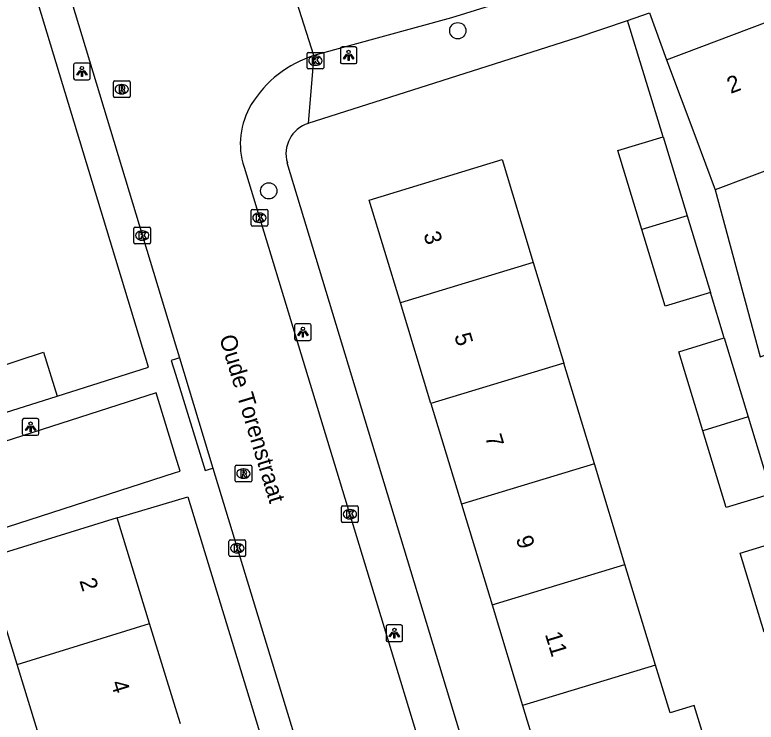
# Model space of a CAD drawing. Extents: x 161253 to 161848, y 384872 to 385383.
# Drawn here: x 161490.34 to 161534.89, y 385004.39 to 385046.88 of the extents above; entities that cross this region are included whole.
import ezdxf

# ---------------------------------------------------------------- set-up
doc = ezdxf.new("R2010")
doc.units = 0
for name, color, linetype in [('IMGEO_Boom', 7, 'Continuous'), ('IMGEO_Kolk', 7, 'Continuous'), ('IMGEO_Lichtpunt', 7, 'Continuous'), ('IMGEO_Openbare_ruimte_label', 7, 'Continuous'), ('IMGEO_Pand', 7, 'Continuous'), ('IMGEO_Pand_nummerreeks', 7, 'Continuous'), ('IMGEO_Rijbaan_lokaal_open', 7, 'Continuous'), ('IMGEO_Rioolput', 7, 'Continuous'), ('IMGEO_Voetpad_open', 7, 'Continuous')]:
    doc.layers.add(name, color=color, linetype=linetype)

msp = doc.modelspace()

# ---------------------------------------------------------------- linework, layer by layer
at = {"layer": 'IMGEO_Boom'}
for centre in [(161516.961, 385045.927), (161505.603, 385036.307)]:
    msp.add_circle(centre, 0.489, dxfattribs=at)
at = {"layer": 'IMGEO_Kolk'}
for p, q in [((161507.901, 385043.701), (161507.901, 385044.553)), ((161507.976, 385044.627), (161508.828, 385044.627)), ((161508.389, 385044.407), (161508.414, 385044.407)), ((161508.902, 385044.553), (161508.902, 385043.701)), ((161508.412, 385043.847), (161508.387, 385043.847)), ((161508.828, 385043.627), (161507.976, 385043.627)), ((161504.541, 385034.269), (161504.541, 385035.121)), ((161504.616, 385035.195), (161505.468, 385035.195)), ((161505.029, 385034.975), (161505.054, 385034.975)), ((161505.542, 385035.121), (161505.542, 385034.269)), ((161505.052, 385034.415), (161505.027, 385034.415)), ((161497.497, 385033.196), (161497.497, 385034.048)), ((161497.572, 385034.122), (161498.424, 385034.122)), ((161498.498, 385034.048), (161498.498, 385033.196)), ((161505.468, 385034.195), (161504.616, 385034.195)), ((161497.985, 385033.902), (161498.01, 385033.902)), ((161498.424, 385033.122), (161497.572, 385033.122)), ((161498.008, 385033.342), (161497.983, 385033.342)), ((161509.976, 385016.457), (161509.976, 385017.309)), ((161510.051, 385017.383), (161510.903, 385017.383)), ((161510.464, 385017.163), (161510.489, 385017.163)), ((161510.977, 385017.309), (161510.977, 385016.457)), ((161510.487, 385016.603), (161510.462, 385016.603)), ((161510.903, 385016.383), (161510.051, 385016.383)), ((161503.212, 385014.414), (161503.212, 385015.266)), ((161503.287, 385015.34), (161504.139, 385015.34)), ((161504.213, 385015.266), (161504.213, 385014.414)), ((161503.7, 385015.12), (161503.725, 385015.12)), ((161503.723, 385014.56), (161503.698, 385014.56)), ((161504.139, 385014.34), (161503.287, 385014.34))]:
    msp.add_line(p, q, dxfattribs=at)
for points in [[(161507.901, 385043.701), (161507.901, 385044.553)], [(161507.976, 385044.627), (161508.828, 385044.627)], [(161508.222, 385044.327), (161508.345, 385044.327), (161508.345, 385044.176), (161508.475, 385044.327), (161508.639, 385044.327), (161508.493, 385044.176), (161508.646, 385043.927), (161508.494, 385043.927), (161508.409, 385044.091), (161508.345, 385044.024), (161508.345, 385043.927), (161508.222, 385043.927), (161508.222, 385044.327)], [(161508.902, 385044.553), (161508.902, 385043.701)], [(161508.828, 385043.627), (161507.976, 385043.627)], [(161504.541, 385034.269), (161504.541, 385035.121)], [(161504.616, 385035.195), (161505.468, 385035.195)], [(161504.862, 385034.895), (161504.985, 385034.895), (161504.985, 385034.744), (161505.115, 385034.895), (161505.279, 385034.895), (161505.133, 385034.744), (161505.286, 385034.495), (161505.134, 385034.495), (161505.049, 385034.659), (161504.985, 385034.592), (161504.985, 385034.495), (161504.862, 385034.495), (161504.862, 385034.895)], [(161505.542, 385035.121), (161505.542, 385034.269)], [(161497.497, 385033.196), (161497.497, 385034.048)], [(161497.572, 385034.122), (161498.424, 385034.122)], [(161498.498, 385034.048), (161498.498, 385033.196)], [(161505.468, 385034.195), (161504.616, 385034.195)], [(161497.818, 385033.822), (161497.941, 385033.822), (161497.941, 385033.671), (161498.071, 385033.822), (161498.235, 385033.822), (161498.089, 385033.671), (161498.242, 385033.422), (161498.09, 385033.422), (161498.005, 385033.586), (161497.941, 385033.519), (161497.941, 385033.422), (161497.818, 385033.422), (161497.818, 385033.822)], [(161498.424, 385033.122), (161497.572, 385033.122)], [(161509.976, 385016.457), (161509.976, 385017.309)], [(161510.051, 385017.383), (161510.903, 385017.383)], [(161510.297, 385017.083), (161510.42, 385017.083), (161510.42, 385016.932), (161510.55, 385017.083), (161510.714, 385017.083), (161510.568, 385016.932), (161510.721, 385016.683), (161510.569, 385016.683), (161510.484, 385016.847), (161510.42, 385016.78), (161510.42, 385016.683), (161510.297, 385016.683), (161510.297, 385017.083)], [(161510.977, 385017.309), (161510.977, 385016.457)], [(161510.903, 385016.383), (161510.051, 385016.383)], [(161503.212, 385014.414), (161503.212, 385015.266)], [(161503.287, 385015.34), (161504.139, 385015.34)], [(161504.213, 385015.266), (161504.213, 385014.414)], [(161503.533, 385015.04), (161503.656, 385015.04), (161503.656, 385014.889), (161503.786, 385015.04), (161503.95, 385015.04), (161503.804, 385014.889), (161503.957, 385014.64), (161503.805, 385014.64), (161503.72, 385014.804), (161503.656, 385014.737), (161503.656, 385014.64), (161503.533, 385014.64), (161503.533, 385015.04)], [(161504.139, 385014.34), (161503.287, 385014.34)]]:
    msp.add_lwpolyline(points, dxfattribs=at)
for centre, start, end in [((161507.978, 385044.551), 91.552, 178.448), ((161507.978, 385044.551), 91.552, 178.448), ((161508.826, 385044.551), 1.552, 88.448), ((161508.826, 385044.551), 1.552, 88.448), ((161507.978, 385043.703), 181.552, 268.448), ((161507.978, 385043.703), 181.552, 268.448), ((161508.826, 385043.703), 271.552, 358.448), ((161508.826, 385043.703), 271.552, 358.448), ((161504.618, 385035.119), 91.552, 178.448), ((161504.618, 385035.119), 91.552, 178.448), ((161505.466, 385035.119), 1.552, 88.448), ((161505.466, 385035.119), 1.552, 88.448), ((161497.574, 385034.046), 91.552, 178.448), ((161497.574, 385034.046), 91.552, 178.448), ((161498.422, 385034.046), 1.552, 88.448), ((161498.422, 385034.046), 1.552, 88.448), ((161504.618, 385034.271), 181.552, 268.448), ((161504.618, 385034.271), 181.552, 268.448), ((161505.466, 385034.271), 271.552, 358.448), ((161505.466, 385034.271), 271.552, 358.448), ((161497.574, 385033.198), 181.552, 268.448), ((161497.574, 385033.198), 181.552, 268.448), ((161498.422, 385033.198), 271.552, 358.448), ((161498.422, 385033.198), 271.552, 358.448), ((161510.053, 385017.307), 91.552, 178.448), ((161510.053, 385017.307), 91.552, 178.448), ((161510.901, 385017.307), 1.552, 88.448), ((161510.901, 385017.307), 1.552, 88.448), ((161510.053, 385016.459), 181.552, 268.448), ((161510.053, 385016.459), 181.552, 268.448), ((161510.901, 385016.459), 271.552, 358.448), ((161510.901, 385016.459), 271.552, 358.448), ((161503.289, 385015.264), 91.552, 178.448), ((161503.289, 385015.264), 91.552, 178.448), ((161504.137, 385015.264), 1.552, 88.448), ((161504.137, 385015.264), 1.552, 88.448), ((161503.289, 385014.416), 181.552, 268.448), ((161503.289, 385014.416), 181.552, 268.448), ((161504.137, 385014.416), 271.552, 358.448), ((161504.137, 385014.416), 271.552, 358.448)]:
    msp.add_arc(centre, 0.0765, start, end, dxfattribs=at)
for centre, major_axis, ratio, start_param, end_param in [((161508.388, 385044.127), (-0.387, 0.002), 0.722429, 4.712389, 7.853982), ((161508.413, 385044.127), (-0.39, 0.002), 0.717154, 1.570796, 4.712389), ((161505.028, 385034.695), (-0.387, 0.002), 0.722429, 4.712389, 7.853982), ((161505.053, 385034.695), (-0.39, 0.002), 0.717154, 1.570796, 4.712389), ((161497.984, 385033.622), (-0.387, 0.002), 0.722429, 4.712389, 7.853982), ((161498.009, 385033.622), (-0.39, 0.002), 0.717154, 1.570796, 4.712389), ((161510.463, 385016.883), (-0.387, 0.002), 0.722429, 4.712389, 7.853982), ((161510.488, 385016.883), (-0.39, 0.002), 0.717154, 1.570796, 4.712389), ((161503.699, 385014.84), (-0.387, 0.002), 0.722429, 4.712389, 7.853982), ((161503.724, 385014.84), (-0.39, 0.002), 0.717154, 1.570796, 4.712389)]:
    msp.add_ellipse(centre, major_axis=major_axis, ratio=ratio, start_param=start_param, end_param=end_param, dxfattribs=at)
at = {"layer": 'IMGEO_Lichtpunt'}
for p, q in [((161509.902, 385044.853), (161509.902, 385044.046)), ((161509.902, 385044.853), (161509.902, 385044.046)), ((161510.804, 385044.948), (161509.996, 385044.948)), ((161510.804, 385044.948), (161509.996, 385044.948)), ((161510.898, 385044.046), (161510.898, 385044.853)), ((161510.898, 385044.046), (161510.898, 385044.853)), ((161493.878, 385043.881), (161493.878, 385043.074)), ((161493.878, 385043.881), (161493.878, 385043.074)), ((161494.78, 385043.976), (161493.972, 385043.976)), ((161494.78, 385043.976), (161493.972, 385043.976)), ((161494.874, 385043.074), (161494.874, 385043.881)), ((161494.874, 385043.074), (161494.874, 385043.881)), ((161509.996, 385043.952), (161510.804, 385043.952)), ((161509.996, 385043.952), (161510.804, 385043.952)), ((161493.972, 385042.98), (161494.78, 385042.98)), ((161493.972, 385042.98), (161494.78, 385042.98)), ((161507.155, 385028.228), (161507.155, 385027.421)), ((161507.155, 385028.228), (161507.155, 385027.421)), ((161508.057, 385028.323), (161507.249, 385028.323)), ((161508.057, 385028.323), (161507.249, 385028.323)), ((161508.151, 385027.421), (161508.151, 385028.228)), ((161508.151, 385027.421), (161508.151, 385028.228)), ((161507.249, 385027.327), (161508.057, 385027.327)), ((161507.249, 385027.327), (161508.057, 385027.327)), ((161490.794, 385022.534), (161490.794, 385021.727)), ((161490.794, 385022.534), (161490.794, 385021.727)), ((161491.696, 385022.629), (161490.888, 385022.629)), ((161491.696, 385022.629), (161490.888, 385022.629)), ((161491.79, 385021.727), (161491.79, 385022.534)), ((161491.79, 385021.727), (161491.79, 385022.534)), ((161490.888, 385021.633), (161491.696, 385021.633)), ((161490.888, 385021.633), (161491.696, 385021.633)), ((161512.649, 385010.134), (161512.649, 385009.327)), ((161512.649, 385010.134), (161512.649, 385009.327)), ((161513.551, 385010.229), (161512.743, 385010.229)), ((161513.551, 385010.229), (161512.743, 385010.229)), ((161513.645, 385009.327), (161513.645, 385010.134)), ((161513.645, 385009.327), (161513.645, 385010.134)), ((161512.743, 385009.233), (161513.551, 385009.233)), ((161512.743, 385009.233), (161513.551, 385009.233))]:
    msp.add_line(p, q, dxfattribs=at)
for points in [[(161510.276, 385044.517), (161510.315, 385044.489), (161510.127, 385044.227), (161510.089, 385044.254), (161510.276, 385044.517)], [(161510.378, 385044.469), (161510.425, 385044.469), (161510.425, 385044.147), (161510.378, 385044.147), (161510.378, 385044.469)], [(161510.488, 385044.489), (161510.526, 385044.516), (161510.713, 385044.254), (161510.674, 385044.226), (161510.488, 385044.489)], [(161494.252, 385043.545), (161494.291, 385043.517), (161494.103, 385043.255), (161494.065, 385043.282), (161494.252, 385043.545)], [(161494.354, 385043.497), (161494.401, 385043.497), (161494.401, 385043.175), (161494.354, 385043.175), (161494.354, 385043.497)], [(161494.464, 385043.517), (161494.502, 385043.544), (161494.689, 385043.282), (161494.65, 385043.254), (161494.464, 385043.517)], [(161507.529, 385027.892), (161507.568, 385027.864), (161507.38, 385027.602), (161507.342, 385027.629), (161507.529, 385027.892)], [(161507.631, 385027.844), (161507.678, 385027.844), (161507.678, 385027.522), (161507.631, 385027.522), (161507.631, 385027.844)], [(161507.741, 385027.864), (161507.779, 385027.891), (161507.966, 385027.629), (161507.927, 385027.601), (161507.741, 385027.864)], [(161491.168, 385022.198), (161491.207, 385022.17), (161491.019, 385021.908), (161490.981, 385021.935), (161491.168, 385022.198)], [(161491.27, 385022.15), (161491.317, 385022.15), (161491.317, 385021.828), (161491.27, 385021.828), (161491.27, 385022.15)], [(161491.38, 385022.17), (161491.418, 385022.197), (161491.605, 385021.935), (161491.566, 385021.907), (161491.38, 385022.17)], [(161513.023, 385009.798), (161513.062, 385009.77), (161512.874, 385009.508), (161512.836, 385009.535), (161513.023, 385009.798)], [(161513.125, 385009.75), (161513.172, 385009.75), (161513.172, 385009.428), (161513.125, 385009.428), (161513.125, 385009.75)], [(161513.235, 385009.77), (161513.273, 385009.797), (161513.46, 385009.535), (161513.421, 385009.507), (161513.235, 385009.77)]]:
    msp.add_lwpolyline(points, dxfattribs=at)
for centre in [(161510.401, 385044.651), (161494.377, 385043.679), (161507.654, 385028.026), (161491.293, 385022.332), (161513.148, 385009.932)]:
    msp.add_circle(centre, 0.0994, dxfattribs=at)
for centre, start, end in [((161509.996, 385044.853), 90, 180), ((161509.996, 385044.853), 90, 180), ((161510.804, 385044.853), 0, 90), ((161510.804, 385044.853), 0, 90), ((161493.972, 385043.881), 90, 180), ((161493.972, 385043.881), 90, 180), ((161494.78, 385043.881), 0, 90), ((161494.78, 385043.881), 0, 90), ((161509.996, 385044.046), 180, 270), ((161509.996, 385044.046), 180, 270), ((161510.804, 385044.046), 270, 0), ((161510.804, 385044.046), 270, 360), ((161493.972, 385043.074), 180, 270), ((161493.972, 385043.074), 180, 270), ((161494.78, 385043.074), 270, 0), ((161494.78, 385043.074), 270, 360), ((161507.249, 385028.228), 90, 180), ((161507.249, 385028.228), 90, 180), ((161508.057, 385028.228), 0, 90), ((161508.057, 385028.228), 0, 90), ((161507.249, 385027.421), 180, 270), ((161507.249, 385027.421), 180, 270), ((161508.057, 385027.421), 270, 0), ((161508.057, 385027.421), 270, 360), ((161490.888, 385022.534), 90, 180), ((161490.888, 385022.534), 90, 180), ((161491.696, 385022.534), 0, 90), ((161491.696, 385022.534), 0, 90), ((161490.888, 385021.727), 180, 270), ((161490.888, 385021.727), 180, 270), ((161491.696, 385021.727), 270, 0), ((161491.696, 385021.727), 270, 360), ((161512.743, 385010.134), 90, 180), ((161512.743, 385010.134), 90, 180), ((161513.551, 385010.134), 0, 90), ((161513.551, 385010.134), 0, 90), ((161512.743, 385009.327), 180, 270), ((161512.743, 385009.327), 180, 270), ((161513.551, 385009.327), 270, 0), ((161513.551, 385009.327), 270, 360)]:
    msp.add_arc(centre, 0.0946, start, end, dxfattribs=at)
at = {"layer": 'IMGEO_Pand'}
for points in [[(161529.493, 385044.181), (161535.556, 385046.459)], [(161529.493, 385044.181), (161531.251, 385039.501), (161532.427, 385036.37)], [(161528.014, 385033.985), (161526.571, 385038.732), (161529.292, 385039.559)], [(161529.292, 385039.559), (161530.735, 385034.812)], [(161538.491, 385038.648), (161532.427, 385036.37)], [(161513.507, 385029.576), (161511.629, 385035.757), (161519.615, 385038.183), (161521.493, 385032.003)], [(161530.735, 385034.812), (161528.014, 385033.985)], [(161530.735, 385034.812), (161532.135, 385030.204)], [(161532.135, 385030.204), (161529.414, 385029.377), (161528.014, 385033.985)], [(161521.493, 385032.003), (161513.507, 385029.576)], [(161521.493, 385032.003), (161523.329, 385025.958)], [(161515.343, 385023.532), (161513.507, 385029.576)], [(161531.686, 385021.897), (161530.243, 385026.644), (161532.964, 385027.471)], [(161532.964, 385027.471), (161534.407, 385022.724)], [(161487.414, 385025.088), (161492.06, 385026.613), (161492.885, 385023.978)], [(161523.329, 385025.958), (161515.343, 385023.532)], [(161525.165, 385019.915), (161523.329, 385025.958)], [(161488.25, 385022.521), (161492.885, 385023.978)], [(161515.343, 385023.532), (161517.18, 385017.488)], [(161534.407, 385022.724), (161531.686, 385021.897)], [(161534.407, 385022.724), (161535.807, 385018.116)], [(161535.807, 385018.116), (161533.086, 385017.289), (161531.686, 385021.897)], [(161525.165, 385019.915), (161517.18, 385017.488)], [(161527.002, 385013.869), (161525.165, 385019.915)], [(161517.18, 385017.488), (161519.016, 385011.443)], [(161496.487, 385016.657), (161488.521, 385014.203)], [(161498.443, 385010.31), (161496.487, 385016.657)], [(161535.365, 385009.797), (161533.921, 385014.549), (161536.611, 385015.367)], [(161490.476, 385007.857), (161488.521, 385014.203)], [(161519.016, 385011.443), (161527.002, 385013.869)], [(161528.842, 385007.815), (161527.002, 385013.869)], [(161519.016, 385011.443), (161520.856, 385005.389)], [(161490.476, 385007.857), (161498.443, 385010.31)], [(161500.299, 385004.283), (161500, 385005.255), (161498.443, 385010.31)], [(161492.311, 385001.903), (161490.476, 385007.857)], [(161528.842, 385007.815), (161520.856, 385005.389)], [(161520.856, 385005.389), (161522.493, 385000), (161522.733, 384999.21), (161525.334, 385000), (161530.719, 385001.636), (161532.174, 385002.078), (161531.166, 385005.396), (161529.711, 385004.954), (161528.842, 385007.815)]]:
    msp.add_lwpolyline(points, dxfattribs=at)
at = {"layer": 'IMGEO_Rijbaan_lokaal_open'}
for points in [[(161508.319, 385044.433), (161506.266, 385050.857)], [(161493.5, 385048.497), (161500, 385027.05), (161500.236, 385026.271)], [(161521.95, 385048.386), (161516.58, 385046.703), (161508.319, 385044.433)], [(161504.114, 385037.727), (161515.595, 385000), (161516.273, 384997.762)], [(161500.236, 385026.271), (161502.25, 385019.651)], [(161470.742, 385008.465), (161470.311, 385009.8), (161500, 385019.381), (161500.269, 385019.47), (161500, 385020.369), (161498.843, 385024.166), (161437.426, 385004.427)], [(161502.25, 385019.651), (161508.229, 385000), (161508.817, 384998.066), (161510.523, 384992.54)]]:
    msp.add_lwpolyline(points, dxfattribs=at)
for centre, radius, start, end in [((161510.34, 385037.969), 6.773, 107.3648, 148.7047), ((161508.413, 385039.131), 4.522, 148.5958, 198.0853)]:
    msp.add_arc(centre, radius, start, end, dxfattribs=at)
at = {"layer": 'IMGEO_Rioolput'}
for p, q in [((161496.342, 385042.913), (161497.194, 385042.913)), ((161496.267, 385041.987), (161496.267, 385042.839)), ((161496.755, 385042.693), (161496.78, 385042.693)), ((161497.268, 385042.839), (161497.268, 385041.987)), ((161496.778, 385042.133), (161496.753, 385042.133)), ((161497.194, 385041.913), (161496.342, 385041.913)), ((161503.579, 385018.895), (161503.579, 385019.747)), ((161503.654, 385019.821), (161504.506, 385019.821)), ((161504.58, 385019.747), (161504.58, 385018.895)), ((161504.067, 385019.601), (161504.092, 385019.601)), ((161504.506, 385018.821), (161503.654, 385018.821)), ((161504.09, 385019.041), (161504.065, 385019.041))]:
    msp.add_line(p, q, dxfattribs=at)
for points in [[(161496.342, 385042.913), (161497.194, 385042.913)], [(161496.267, 385041.987), (161496.267, 385042.839)], [(161496.856, 385042.611), (161496.604, 385042.613), (161496.604, 385042.213)], [(161496.782, 385042.532), (161496.728, 385042.532), (161496.728, 385042.451)], [(161496.728, 385042.451), (161496.78, 385042.451)], [(161497.268, 385042.839), (161497.268, 385041.987)], [(161496.604, 385042.213), (161496.728, 385042.213), (161496.728, 385042.375), (161496.739, 385042.375)], [(161496.786, 385042.346), (161496.857, 385042.213), (161496.997, 385042.213), (161496.932, 385042.339)], [(161497.194, 385041.913), (161496.342, 385041.913)], [(161503.579, 385018.895), (161503.579, 385019.747)], [(161503.654, 385019.821), (161504.506, 385019.821)], [(161504.58, 385019.747), (161504.58, 385018.895)], [(161504.168, 385019.519), (161503.916, 385019.521), (161503.916, 385019.121)], [(161503.916, 385019.121), (161504.04, 385019.121), (161504.04, 385019.283), (161504.051, 385019.283)], [(161504.094, 385019.44), (161504.04, 385019.44), (161504.04, 385019.359)], [(161504.04, 385019.359), (161504.092, 385019.359)], [(161504.098, 385019.254), (161504.169, 385019.121), (161504.309, 385019.121), (161504.244, 385019.247)], [(161504.506, 385018.821), (161503.654, 385018.821)]]:
    msp.add_lwpolyline(points, dxfattribs=at)
for centre, radius, start, end in [((161496.344, 385042.837), 0.0765, 91.552, 178.448), ((161496.344, 385042.837), 0.0765, 91.552, 178.448), ((161497.192, 385042.837), 0.0765, 1.552, 88.448), ((161497.192, 385042.837), 0.0765, 1.552, 88.448), ((161496.764, 385042.64), 0.19, 274.7715, 282.9687), ((161496.788, 385042.436), 0.0964, 77.0061, 93.1865), ((161496.802, 385042.493), 0.0378, 276.6634, 79.6772), ((161496.855, 385042.501), 0.109, 350.3612, 89.416), ((161496.853, 385042.501), 0.112, 277.5842, 350.9817), ((161496.344, 385041.989), 0.0765, 181.552, 268.448), ((161496.344, 385041.989), 0.0765, 181.552, 268.448), ((161496.738, 385042.322), 0.0533, 26.0293, 88.6989), ((161496.837, 385042.286), 0.108, 29.5134, 73.7905), ((161497.192, 385041.989), 0.0765, 271.552, 358.448), ((161497.192, 385041.989), 0.0765, 271.552, 358.448), ((161503.656, 385019.745), 0.0765, 91.552, 178.448), ((161503.656, 385019.745), 0.0765, 91.552, 178.448), ((161504.504, 385019.745), 0.0765, 1.552, 88.448), ((161504.504, 385019.745), 0.0765, 1.552, 88.448), ((161504.05, 385019.23), 0.0533, 26.0293, 88.6989), ((161504.076, 385019.548), 0.19, 274.7715, 282.9687), ((161504.1, 385019.344), 0.0964, 77.0061, 93.1865), ((161504.114, 385019.401), 0.0378, 276.6634, 79.6772), ((161504.167, 385019.409), 0.109, 350.3612, 89.416), ((161504.165, 385019.409), 0.112, 277.5842, 350.9817), ((161504.149, 385019.194), 0.108, 29.5134, 73.7905), ((161503.656, 385018.897), 0.0765, 181.552, 268.448), ((161503.656, 385018.897), 0.0765, 181.552, 268.448), ((161504.504, 385018.897), 0.0765, 271.552, 358.448), ((161504.504, 385018.897), 0.0765, 271.552, 358.448)]:
    msp.add_arc(centre, radius, start, end, dxfattribs=at)
for centre, major_axis, ratio, start_param, end_param in [((161496.754, 385042.413), (-0.387, 0.002), 0.722429, 4.712389, 7.853982), ((161496.779, 385042.413), (-0.39, 0.002), 0.717154, 1.570796, 4.712389), ((161504.066, 385019.321), (-0.387, 0.002), 0.722429, 4.712389, 7.853982), ((161504.091, 385019.321), (-0.39, 0.002), 0.717154, 1.570796, 4.712389)]:
    msp.add_ellipse(centre, major_axis=major_axis, ratio=ratio, start_param=start_param, end_param=end_param, dxfattribs=at)
at = {"layer": 'IMGEO_Voetpad_open'}
for points in [[(161492.885, 385023.978), (161498.371, 385025.726), (161491.075, 385049.831)], [(161527.147, 385046.532), (161528.473, 385047.01)], [(161528.473, 385047.01), (161529.493, 385044.181)], [(161507.972, 385040.363), (161524.135, 385045.511), (161527.147, 385046.532)], [(161529.292, 385039.559), (161527.147, 385046.532)], [(161508.319, 385044.433), (161507.972, 385040.363)], [(161518.805, 384998.06), (161518.218, 385000), (161506.717, 385037.985)], [(161532.427, 385036.37), (161535.134, 385026.331), (161537.701, 385027.25)], [(161532.964, 385027.471), (161532.135, 385030.204)], [(161500.236, 385026.271), (161500, 385026.199), (161499.746, 385026.121), (161500, 385025.292), (161501.773, 385019.505), (161502.25, 385019.651)], [(161496.487, 385016.657), (161500, 385017.708), (161500.743, 385017.93), (161506.207, 385000), (161508.211, 384993.423), (161504.045, 384992.126)]]:
    msp.add_lwpolyline(points, dxfattribs=at)
msp.add_arc((161508.551, 385038.537), 1.915, 107.5984, 196.7555, dxfattribs=at)

# ---------------------------------------------------------------- texts
at = {"layer": 'IMGEO_Openbare_ruimte_label'}
msp.add_text('Oude Torenstraat', height=1, rotation=286.9132, dxfattribs=at).set_placement((161502.617, 385027.502))
at = {"layer": 'IMGEO_Pand_nummerreeks'}
for s, rotation, p in [('2', 20.5888, (161533.352, 385042.127)), ('3', 286.9003, (161514.886, 385033.707)), ('5', 286.9003, (161516.737, 385027.616)), ('7', 286.9003, (161518.587, 385021.525)), ('9', 286.9003, (161520.438, 385015.434)), ('2', 287.1241, (161494.216, 385012.89)), ('11', 286.9003, (161522.188, 385009.674)), ('4', 287.1241, (161496.106, 385006.755))]:
    msp.add_text(s, height=1, rotation=rotation, dxfattribs=at).set_placement(p)

doc.saveas('drawing.dxf')
